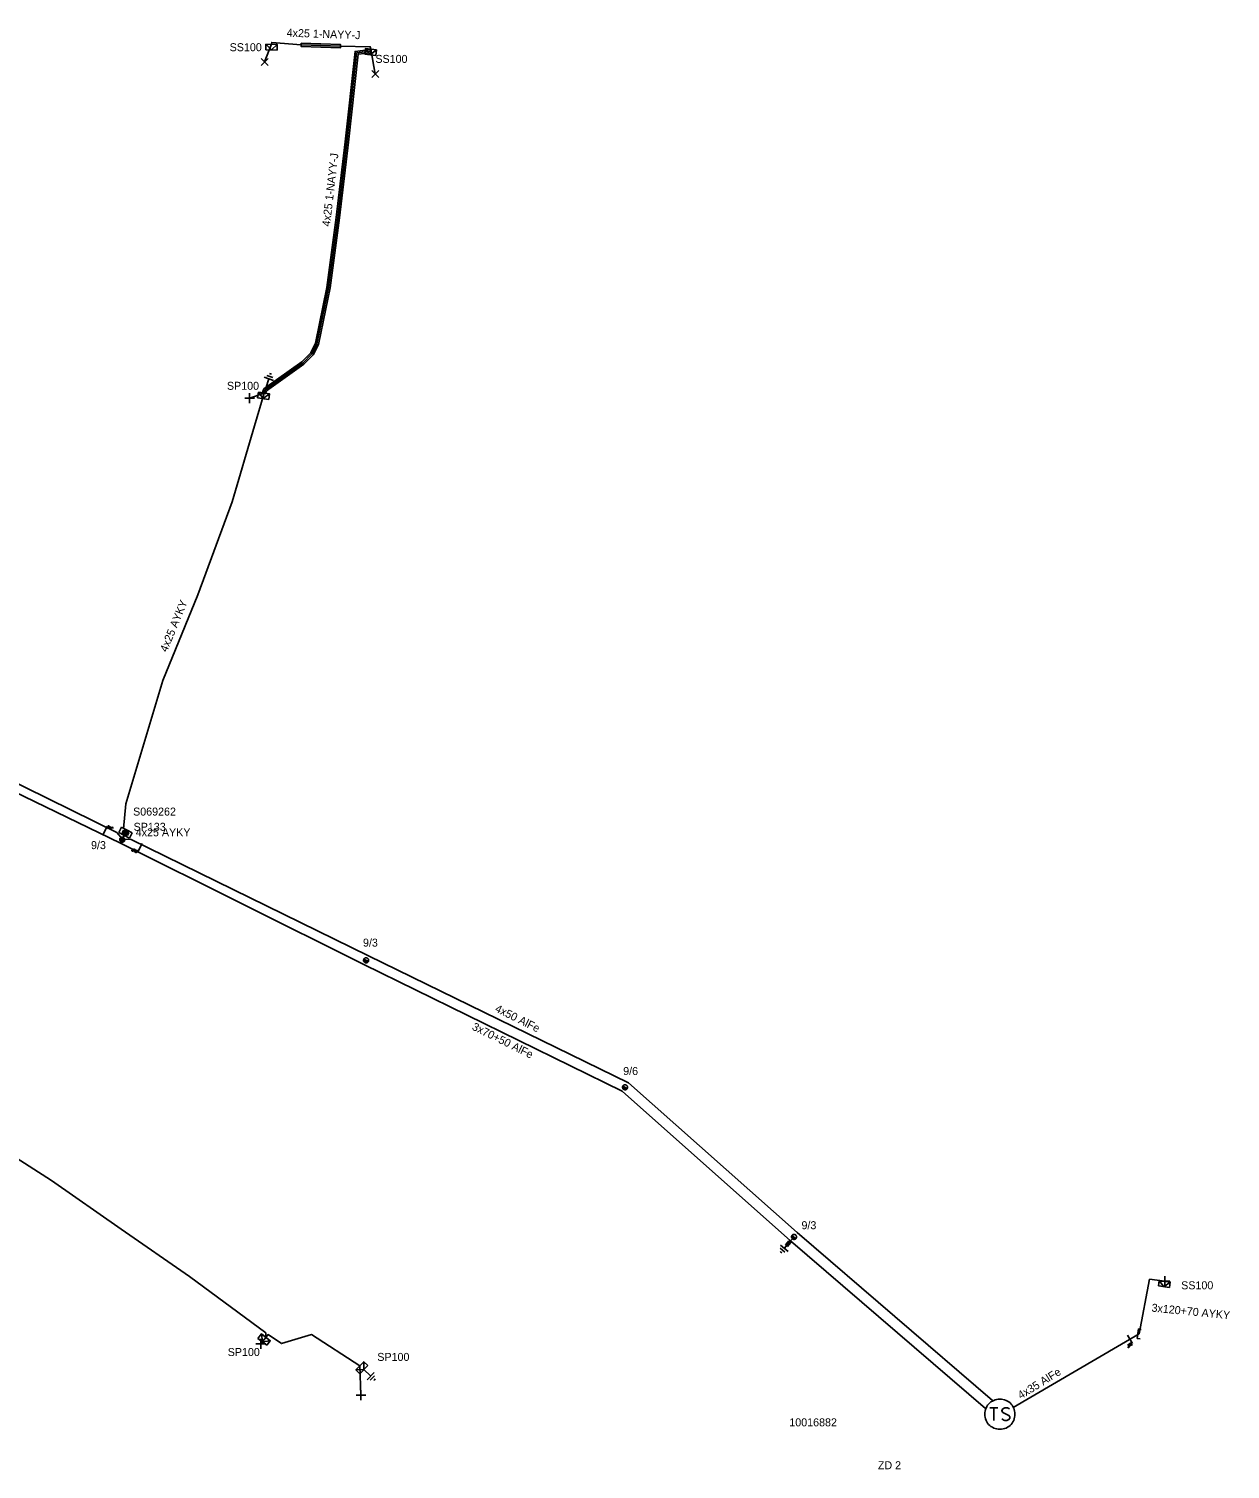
# Model space of a CAD drawing. Extents: x -717562 to -713845, y -1151196 to -1143903.
# Drawn here: x -716879.6 to -716729.4, y -1145171.2 to -1144991.1 of the extents above; entities that cross this region are included whole.
import ezdxf

# ---------------------------------------------------------------- set-up
doc = ezdxf.new("R2010")
doc.units = 0
for name, color, linetype in [('Vrstva 1', 7, 'Continuous'), ('Vrstva 12', 7, 'Continuous'), ('Vrstva 13', 7, 'Continuous'), ('Vrstva 14', 7, 'Continuous'), ('Vrstva 15', 7, 'Continuous'), ('Vrstva 16', 7, 'Continuous'), ('Vrstva 18', 7, 'Continuous'), ('Vrstva 2', 7, 'Continuous'), ('Vrstva 20', 7, 'Continuous'), ('Vrstva 25', 7, 'Continuous'), ('Vrstva 26', 7, 'Continuous'), ('Vrstva 27', 7, 'Continuous'), ('Vrstva 28', 7, 'Continuous'), ('Vrstva 29', 7, 'Continuous'), ('Vrstva 30', 7, 'Continuous'), ('Vrstva 31', 7, 'Continuous'), ('Vrstva 33', 7, 'Continuous'), ('Vrstva 34', 7, 'Continuous'), ('Vrstva 5', 7, 'Continuous'), ('Vrstva 52', 7, 'Continuous'), ('Vrstva 54', 7, 'Continuous'), ('Vrstva 59', 7, 'Continuous'), ('Vrstva 6', 7, 'Continuous'), ('Vrstva 8', 7, 'Continuous'), ('Vrstva 9', 7, 'Continuous')]:
    doc.layers.add(name, color=color, linetype=linetype)

# ---------------------------------------------------------------- blocks, each defined once
blk = doc.blocks.new('NN440')
at = {"layer": 'Vrstva 2'}
for points in [[(0.63, 0), (0.63, 0.06), (0.62, 0.13), (0.6, 0.19), (0.58, 0.25), (0.55, 0.31), (0.51, 0.37), (0.47, 0.42), (0.42, 0.46), (0.37, 0.51), (0.32, 0.54), (0.26, 0.57), (0.2, 0.59), (0.13, 0.61), (0.07, 0.62), (0, 0.63), (-0.06, 0.62), (-0.13, 0.61), (-0.19, 0.59), (-0.26, 0.57), (-0.31, 0.54), (-0.37, 0.51), (-0.42, 0.46), (-0.47, 0.42), (-0.51, 0.37), (-0.54, 0.31), (-0.57, 0.25), (-0.6, 0.19), (-0.62, 0.13), (-0.63, 0.06), (-0.63, 0), (-0.63, -0.07), (-0.62, -0.14), (-0.6, -0.2), (-0.57, -0.26), (-0.54, -0.32), (-0.51, -0.37), (-0.47, -0.43), (-0.42, -0.47), (-0.37, -0.51), (-0.31, -0.55), (-0.26, -0.58), (-0.19, -0.6), (-0.13, -0.62), (-0.06, -0.63), (0, -0.63), (0.07, -0.63), (0.13, -0.62), (0.2, -0.6), (0.26, -0.58), (0.32, -0.55), (0.37, -0.51), (0.42, -0.47), (0.47, -0.43), (0.51, -0.37), (0.55, -0.32), (0.58, -0.26), (0.6, -0.2), (0.62, -0.14), (0.63, -0.07), (0.63, 0)], [(-0.63, 0), (0.63, 0)], [(-0.6, -0.18), (0.57, -0.18)], [(-0.51, -0.32), (0.5, -0.32)], [(-0.37, -0.47), (0.35, -0.47)]]:
    blk.add_lwpolyline(points, dxfattribs=at)
blk = doc.blocks.new('NN840')
at = {"layer": 'Vrstva 15'}
for points in [[(0, 0.62), (0, -0.63)], [(-0.75, -0.71), (-0.75, -0.66)], [(-0.73, -0.76), (-0.75, -0.71)], [(-0.66, -0.8), (-0.73, -0.76)], [(-0.63, -0.8), (-0.66, -0.8)], [(-0.56, -0.76), (-0.63, -0.8)], [(-0.54, -0.71), (-0.56, -0.76)], [(-0.54, -0.38), (-0.54, -0.71)], [(-0.33, -0.38), (-0.33, -0.8)], [(-0.33, -0.64), (-0.13, -0.38)], [(-0.26, -0.56), (-0.09, -0.8)]]:
    blk.add_lwpolyline(points, dxfattribs=at)
blk = doc.blocks.new('NN800')
at = {"layer": 'Vrstva 1'}
for points in [[(-0.44, 0.44), (0.44, -0.44)], [(-0.44, -0.44), (0.44, 0.44)]]:
    blk.add_lwpolyline(points, dxfattribs=at)
blk = doc.blocks.new('NN820')
at = {"layer": 'Vrstva 13'}
for points in [[(0, 0), (0, -1.05)], [(-0.16, -0.81), (0.16, -0.81)], [(-0.16, -1.47), (-0.16, -0.81)], [(0.16, -1.47), (-0.16, -1.47)], [(0, -1.05), (-0.06, -0.93)], [(0, -1.05), (0.06, -0.93)], [(0, -1.47), (0, -1.87)], [(0.16, -0.81), (0.16, -1.47)]]:
    blk.add_lwpolyline(points, dxfattribs=at)
blk = doc.blocks.new('NN620')
at = {"layer": 'Vrstva 8'}
for points in [[(0.75, 0), (-0.75, 0)], [(-0.75, 0), (-0.75, -0.75)], [(0.75, -0.75), (0.75, 0)], [(-0.75, -0.75), (0.75, -0.75)], [(0.37, -0.18), (-0.38, -0.18)], [(-0.38, -0.18), (-0.38, -0.56)], [(-0.38, -0.56), (0.37, -0.56)], [(0.32, -0.23), (-0.33, -0.23)], [(-0.33, -0.23), (-0.33, -0.51)], [(-0.33, -0.51), (0.32, -0.51)], [(0.27, -0.27), (-0.28, -0.27)], [(-0.28, -0.27), (-0.28, -0.46)], [(-0.28, -0.46), (0.27, -0.46)], [(0.23, -0.32), (-0.23, -0.32)], [(-0.23, -0.32), (-0.23, -0.42)], [(-0.23, -0.42), (0.23, -0.42)], [(-0.19, -0.37), (0.19, -0.37)], [(0.23, -0.42), (0.23, -0.32)], [(0.27, -0.46), (0.27, -0.27)], [(0.32, -0.51), (0.32, -0.23)], [(0.37, -0.56), (0.37, -0.18)]]:
    blk.add_lwpolyline(points, dxfattribs=at)
blk = doc.blocks.new('NN630')
at = {"layer": 'Vrstva 9'}
for points in [[(0, -0.7), (-0.7, 0)], [(-0.7, -0.7), (-0.7, 0), (0.7, 0), (0.7, -0.7)], [(-0.7, -0.7), (0.7, -0.7)], [(0, -0.7), (0.7, 0)]]:
    blk.add_lwpolyline(points, dxfattribs=at)
blk = doc.blocks.new('NN810')
at = {"layer": 'Vrstva 14'}
for points in [[(0, -0.64), (0, -1.89)], [(0.63, -1.89), (-0.62, -1.89)], [(0.39, -2.2), (-0.4, -2.2)], [(0, -2.52), (-0.12, -2.52)], [(0.14, -2.52), (0, -2.52)]]:
    blk.add_lwpolyline(points, dxfattribs=at)
blk = doc.blocks.new('NN610')
at = {"layer": 'Vrstva 6'}
for points in [[(1.88, 0), (1.87, 0.2), (1.84, 0.39), (1.79, 0.58), (1.72, 0.77), (1.63, 0.94), (1.52, 1.11), (1.4, 1.26), (1.26, 1.4), (1.1, 1.53), (0.94, 1.63), (0.76, 1.72), (0.58, 1.8), (0.19, 1.88), (0.19, 1.88), (-0.01, 1.89), (-0.21, 1.88), (-0.4, 1.85), (-0.59, 1.8), (-0.78, 1.72), (-0.95, 1.63), (-1.12, 1.53), (-1.27, 1.4), (-1.41, 1.26), (-1.54, 1.11), (-1.64, 0.94), (-1.73, 0.77), (-1.8, 0.58), (-1.86, 0.39), (-1.89, 0.2), (-1.9, 0), (-1.89, -0.2), (-1.86, -0.39), (-1.8, -0.58), (-1.73, -0.77), (-1.64, -0.95), (-1.54, -1.11), (-1.41, -1.27), (-1.27, -1.41), (-1.12, -1.53), (-0.95, -1.64), (-0.78, -1.73), (-0.59, -1.8), (-0.4, -1.85), (-0.21, -1.88), (-0.01, -1.89), (0.19, -1.88), (0.39, -1.85), (0.58, -1.8), (0.76, -1.73), (0.94, -1.64), (1.1, -1.53), (1.26, -1.41), (1.4, -1.27), (1.52, -1.11), (1.63, -0.95), (1.72, -0.77), (1.79, -0.58), (1.84, -0.39), (1.87, -0.2), (1.88, 0)], [(-1.27, 0.78), (-0.26, 0.78)], [(-0.76, 0.78), (-0.76, -0.79)], [(1.19, 0.66), (0.94, 0.78), (0.62, 0.78), (0.37, 0.66), (0.24, 0.47), (0.24, 0.4), (0.37, 0.22), (1.12, -0.16), (1.25, -0.32), (1.25, -0.48), (1.12, -0.67), (0.87, -0.79), (0.62, -0.79), (0.49, -0.73), (0.24, -0.6)]]:
    blk.add_lwpolyline(points, dxfattribs=at)
blk = doc.blocks.new('NN515')
at = {"layer": 'Vrstva 2'}
for points in [[(-0.59, 0.18), (0.59, 0.18)], [(-0.59, 0.18), (-0.59, -0.18)], [(0.59, 0.18), (0.59, -0.18)]]:
    blk.add_lwpolyline(points, dxfattribs=at)

msp = doc.modelspace()

# ---------------------------------------------------------------- linework, layer by layer
at = {"layer": 'Vrstva 1'}
for points in [[(-716867.87, -1145092.44), (-716868.57, -1145091.59), (-716897.18, -1145077.53), (-716943.12, -1145070.58), (-716975.82, -1145066.66)], [(-716759.95, -1145163.6), (-716784.34, -1145142.64), (-716805.38, -1145123.94), (-716837.68, -1145108.1), (-716868.11, -1145092.94), (-716897.56, -1145078.69), (-716942.42, -1145071.73)], [(-716759.07, -1145162.58), (-716783.51, -1145141.58), (-716804.6, -1145122.89), (-716837.09, -1145107), (-716866.76, -1145092.48), (-716867.87, -1145092.44)], [(-716756.52, -1145163.46), (-716740.74, -1145154.26)]]:
    msp.add_lwpolyline(points, dxfattribs=at)
at = {"layer": 'Vrstva 20'}
for points in [[(-716836.83, -1144994.14), (-716838.41, -1144994.33), (-716839.62, -1145005.29), (-716840.73, -1145014.78), (-716841.9, -1145023.52), (-716843.36, -1145030.59), (-716844.01, -1145031.87), (-716845.19, -1145033.07), (-716849.86, -1145036.41), (-716849.97, -1145036.73), (-716850.35, -1145036.61), (-716850.2, -1145036.15), (-716845.45, -1145032.77), (-716844.33, -1145031.63), (-716843.74, -1145030.45), (-716842.3, -1145023.46), (-716841.13, -1145014.74), (-716840.02, -1145005.25), (-716838.77, -1144993.97), (-716836.87, -1144993.74)], [(-716845.51, -1144992.95), (-716840.59, -1144993.12), (-716840.61, -1144993.52), (-716845.53, -1144993.35)]]:
    msp.add_lwpolyline(points, close=True, dxfattribs=at)
at = {"layer": 'Vrstva 5'}
for points in [[(-716850.16, -1145036.67), (-716850.03, -1145036.28), (-716845.32, -1145032.92), (-716844.17, -1145031.75), (-716843.55, -1145030.52), (-716842.1, -1145023.49), (-716840.93, -1145014.76), (-716839.82, -1145005.27), (-716838.59, -1144994.15), (-716836.85, -1144993.94), (-716836.8, -1144993.69)], [(-716836.8, -1144993.69), (-716836.88, -1144993.38), (-716840.6, -1144993.32), (-716845.52, -1144993.15), (-716849.2, -1144992.84), (-716849.22, -1144993.08)], [(-716867.75, -1145091.15), (-716867.44, -1145088.02), (-716862.81, -1145072.59), (-716858.42, -1145061.89), (-716854.16, -1145050.28), (-716851.37, -1145040.76), (-716850.16, -1145036.67)], [(-716867.87, -1145092.44), (-716867.65, -1145091.95)], [(-716838.19, -1145158.25), (-716844.21, -1145154.36), (-716847.99, -1145155.48), (-716849.66, -1145154.36), (-716849.94, -1145154.7), (-716849.95, -1145154.14), (-716859.5, -1145147.1), (-716868.03, -1145141.17), (-716876.74, -1145135.11), (-716884, -1145130.48), (-716899.81, -1145119.57), (-716906.11, -1145117.17), (-716907.15, -1145117.93), (-716906.15, -1145124.61), (-716904.93, -1145131.77), (-716909.53, -1145133.02)]]:
    msp.add_lwpolyline(points, dxfattribs=at)
at = {"layer": 'Vrstva 52'}
msp.add_lwpolyline([(-716740.74, -1145154.26), (-716739.46, -1145147.43), (-716737.56, -1145147.68)], dxfattribs=at)
at = {"layer": 'Vrstva 59'}
for points in [[(-716849.22, -1144993.08), (-716850.1, -1144995.28)], [(-716836.8, -1144993.69), (-716836.26, -1144996.79)], [(-716850.16, -1145036.67), (-716851.96, -1145037.31)], [(-716849.94, -1145154.7), (-716850.55, -1145155.49)], [(-716838.19, -1145158.25), (-716838.04, -1145161.92)]]:
    msp.add_lwpolyline(points, dxfattribs=at)

# ---------------------------------------------------------------- block references
at = {"layer": 'Vrstva 13', "xscale": 0.5}
for p, yscale, rotation in [((-716867.89, -1145092.49), 0.5000000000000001, -26.20727221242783), ((-716837.4, -1145107.57), 0.5000000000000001, -26.20727221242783), ((-716805.03, -1145123.44), 0.5, -26.207272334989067), ((-716783.9, -1145142.14), 0.5000000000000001, -40.73182770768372)]:
    msp.add_blockref('NN440', p, dxfattribs=dict(at, yscale=yscale, rotation=rotation))
at = {"layer": 'Vrstva 13', "rotation": 82.45780839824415}
msp.add_blockref('NN515', (-716740.74, -1145154.26), dxfattribs=at)
at = {"layer": 'Vrstva 15'}
for p, rotation in [((-716850.16, -1145036.67), 161.33225002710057), ((-716783.9, -1145142.14), -40.730774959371), ((-716838.19, -1145158.25), 46.17727218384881)]:
    msp.add_blockref('NN810', p, dxfattribs=dict(at, rotation=rotation))
at = {"layer": 'Vrstva 16', "rotation": -40.73077510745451}
msp.add_blockref('NN820', (-716783.9, -1145142.14), dxfattribs=at)
at = {"layer": 'Vrstva 18'}
for p, rotation in [((-716870.04, -1145091.37), 153.69374170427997), ((-716865.69, -1145093.51), -26.306258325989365), ((-716741.9, -1145154.94), 30.242012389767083)]:
    msp.add_blockref('NN840', p, dxfattribs=dict(at, rotation=rotation))
at = {"layer": 'Vrstva 25'}
msp.add_blockref('NN610', (-716758.16, -1145164.3), dxfattribs=at)
at = {"layer": 'Vrstva 28', "rotation": 153.23982885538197}
msp.add_blockref('NN620', (-716867.65, -1145091.95), dxfattribs=at)
at = {"layer": 'Vrstva 31'}
for p, rotation in [((-716849.22, -1144993.08), -0.7639048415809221), ((-716836.8, -1144993.69), -6.589733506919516), ((-716850.16, -1145036.67), -9.20691103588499), ((-716737.56, -1145147.68), -8.103261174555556), ((-716849.94, -1145154.7), -37.83826948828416), ((-716838.19, -1145158.25), 46.17727218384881)]:
    msp.add_blockref('NN630', p, dxfattribs=dict(at, rotation=rotation))
at = {"layer": 'Vrstva 34'}
for p in [(-716850.1, -1144995.28), (-716836.26, -1144996.79)]:
    msp.add_blockref('NN800', p, dxfattribs=at)
for p, rotation in [((-716851.96, -1145037.31), 45), ((-716737.56, -1145147.68), 45.00000009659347), ((-716850.55, -1145155.49), 44.99999995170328), ((-716838.04, -1145161.92), 45)]:
    msp.add_blockref('NN800', p, dxfattribs=dict(at, rotation=rotation))

# ---------------------------------------------------------------- texts
at = {"layer": 'Vrstva 12'}
for s, p in [('9/3', (-716871.79, -1145093.67)), ('9/3', (-716837.79, -1145105.86)), ('9/6', (-716805.26, -1145121.91)), ('9/3', (-716782.97, -1145141.18))]:
    msp.add_text(s, height=1, dxfattribs=at).set_placement(p)
at = {"layer": 'Vrstva 2'}
for s, rotation, p in [('4x50 AlFe', 333.595, (-716821.38, -1145113.93)), ('3x70+50 AlFe', 333.594, (-716824.25, -1145116.19)), ('4x35 AlFe', 31.84, (-716755.54, -1145162.46))]:
    msp.add_text(s, height=1, rotation=rotation, dxfattribs=at).set_placement(p)
at = {"layer": 'Vrstva 26'}
msp.add_text('10016882', height=1, dxfattribs=at).set_placement((-716784.49, -1145165.82))
at = {"layer": 'Vrstva 27'}
msp.add_text('ZD 2', height=1, dxfattribs=at).set_placement((-716773.42, -1145171.18))
at = {"layer": 'Vrstva 29'}
msp.add_text('S069262', height=1, dxfattribs=at).set_placement((-716866.53, -1145089.48))
at = {"layer": 'Vrstva 30'}
msp.add_text('SP133', height=1, dxfattribs=at).set_placement((-716866.47, -1145091.38))
at = {"layer": 'Vrstva 33'}
for s, p in [('SS100', (-716854.46, -1144993.94)), ('SS100', (-716836.24, -1144995.4)), ('SP100', (-716854.8, -1145036.26)), ('SS100', (-716735.5, -1145148.69)), ('SP100', (-716854.7, -1145157.03)), ('SP100', (-716836, -1145157.64))]:
    msp.add_text(s, height=1, dxfattribs=at).set_placement(p)
at = {"layer": 'Vrstva 54'}
msp.add_text('3x120+70 AYKY', height=1, rotation=354.374, dxfattribs=at).set_placement((-716739.24, -1145151.47))
at = {"layer": 'Vrstva 6'}
for s, rotation, p in [('4x25 1-NAYY-J', 358.021, (-716847.34, -1144992.12)), ('4x25 1-NAYY-J', 83.329, (-716841.92, -1145015.89)), ('4x25 AYKY', 67.692, (-716862.3, -1145069.12))]:
    msp.add_text(s, height=1, rotation=rotation, dxfattribs=at).set_placement(p)
msp.add_text('4x25 AYKY', height=1, dxfattribs=at).set_placement((-716866.2, -1145092.07))

doc.saveas('drawing.dxf')
